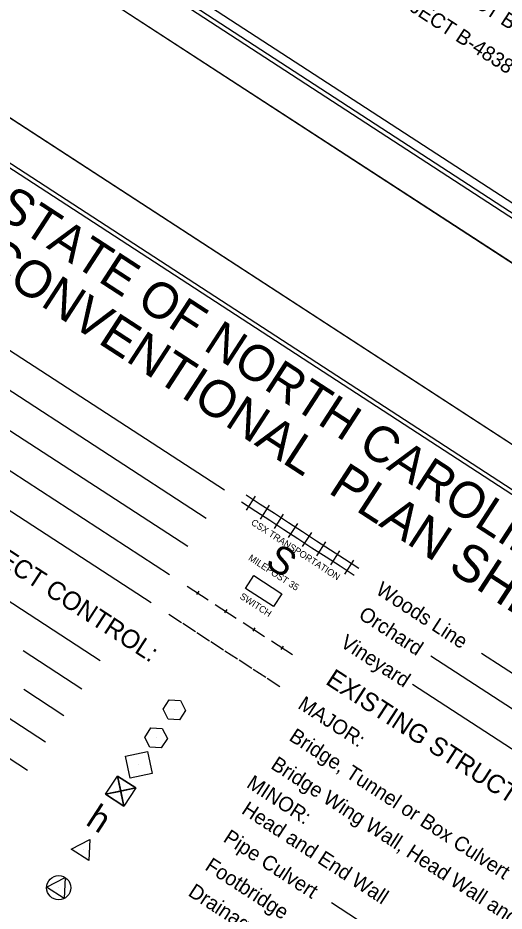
# Model space of a CAD drawing. Extents: x 2291197 to 2302790, y 592892 to 604246.
# Drawn here: x 2295608 to 2296768, y 597065 to 599195 of the extents above; entities that cross this region are included whole.
import ezdxf

# ---------------------------------------------------------------- set-up
doc = ezdxf.new("R2010")
doc.units = 0
for name, color, linetype in [('Default', 7, 'Continuous'), ('Prop Shade Light', 7, 'Continuous'), ('Sheet Cutting Line CELL', 7, 'Continuous'), ('Sheet Plot Border Inside CELL', 7, 'Continuous'), ('Sheet Plot Border Outside CELL', 7, 'Continuous'), ('Sheet Symbology CELL', 7, 'Continuous'), ('Sheet Title CELL', 7, 'Continuous')]:
    doc.layers.add(name, color=color, linetype=linetype)

# ---------------------------------------------------------------- blocks, each defined once
blk = doc.blocks.new('RWCON')
at = {"layer": 'Sheet Symbology CELL'}
blk.add_line((0, 0), (0, 0), dxfattribs=at)
blk.add_lwpolyline([(-0.125, -0.072), (0, 0.144), (0.125, -0.072)], close=True, dxfattribs=at)
blk.add_circle((0, 0), 0.144, dxfattribs=at)
blk = doc.blocks.new('CTL SECONDARY HORIZONTAL AND VERTICAL')
at = {"layer": 'Default'}
blk.add_line((0, 0), (0, 0), dxfattribs=at)
blk.add_lwpolyline([(-0.0735, 0.074), (0.07475, 0.074), (0.07475, -0.0745), (-0.0735, -0.0745)], close=True, dxfattribs=at)
blk = doc.blocks.new('CTL PRIMARY HORIZONTAL')
at = {"layer": 'Default'}
blk.add_line((0, 0), (0, 0), dxfattribs=at)
blk.add_lwpolyline([(0, -0.07375), (-0.06425, -0.03725), (-0.06425, 0.0365), (0, 0.07375), (0.06425, 0.03725), (0.06425, -0.03725), (0, -0.07375)], dxfattribs=at)
blk = doc.blocks.new('CTL PRIMARY HORIZONTAL AND VERTICAL')
at = {"layer": 'Default'}
blk.add_line((0, 0), (0, 0), dxfattribs=at)
blk.add_lwpolyline([(-0.0646, 0.0374), (0.0004, 0.0737), (0.0654, 0.0379), (0.0644, -0.0366), (-0.0006, -0.0743), (-0.0646, -0.0381)], close=True, dxfattribs=at)
blk = doc.blocks.new('CTL VERTICAL BENCHMARK')
at = {"layer": 'Default'}
blk.add_line((0, 0), (0, 0), dxfattribs=at)
blk.add_lwpolyline([(-0.072, 0.07175), (0.07175, 0.07175), (0.07175, -0.072), (-0.072, -0.072)], close=True, dxfattribs=at)
for points in [[(0.07175, 0.07175), (-0.072, -0.072), (-0.000125, -0.000125), (0.07175, -0.072), (-0.072, 0.07175)], [(-0.000125, -0.000125), (0.07175, 0.07175), (-0.072, 0.07175), (-0.000125, -0.000125)], [(-0.000125, -0.000125), (-0.072, -0.072), (0.07175, -0.072), (-0.000125, -0.000125)]]:
    blk.add_lwpolyline(points, dxfattribs=at)
blk = doc.blocks.new('PRRM')
at = {"layer": 'Sheet Symbology CELL'}
blk.add_line((0, 0), (0, 0), dxfattribs=at)
blk.add_lwpolyline([(-0.125, -0.072), (0, 0.144), (0.125, -0.072)], close=True, dxfattribs=at)
blk = doc.blocks.new('PLAN SHEET SYMBOLOGY - New')
at = {"layer": 'Sheet Cutting Line CELL'}
blk.add_line((1439376.56, 921733.15), (1437692.56, 921733.15), dxfattribs=at)
at = {"layer": 'Sheet Plot Border Inside CELL'}
blk.add_lwpolyline([(1437705.56, 920655.6), (1439372.06, 920655.6), (1439372.06, 921710.7), (1437705.56, 921710.7)], close=True, dxfattribs=at)
at = {"layer": 'Sheet Plot Border Outside CELL'}
blk.add_lwpolyline([(1437692.56, 920633.15), (1439376.56, 920633.15), (1439376.56, 921733.15), (1437692.56, 921733.15)], close=True, dxfattribs=at)
at = {"layer": 'Sheet Symbology CELL'}
for p, q in [((1438527.58, 921621.6), (1438537.58, 921621.6)), ((1438532.58, 921614.1), (1438532.58, 921624.1)), ((1438537.58, 921621.6), (1438547.58, 921621.6)), ((1438542.58, 921614.1), (1438542.58, 921624.1)), ((1438547.58, 921621.6), (1438557.58, 921621.6)), ((1438552.58, 921614.1), (1438552.58, 921624.1)), ((1438557.58, 921621.6), (1438567.58, 921621.6)), ((1438562.58, 921614.1), (1438562.58, 921624.1)), ((1438567.58, 921621.6), (1438577.58, 921621.6)), ((1438572.58, 921614.1), (1438572.58, 921624.1)), ((1438577.58, 921621.6), (1438587.58, 921621.6)), ((1438582.58, 921614.1), (1438582.58, 921624.1)), ((1438587.58, 921621.6), (1438597.58, 921621.6)), ((1438592.58, 921614.1), (1438592.58, 921624.1)), ((1438597.58, 921621.6), (1438607.58, 921621.6)), ((1438602.58, 921614.1), (1438602.58, 921624.1)), ((1438515.19, 921616.84), (1438356.78, 921616.84)), ((1438527.58, 921616.6), (1438537.58, 921616.6)), ((1438537.58, 921616.6), (1438547.58, 921616.6)), ((1438547.58, 921616.6), (1438557.58, 921616.6)), ((1438557.58, 921616.6), (1438567.58, 921616.6)), ((1438567.58, 921616.6), (1438577.58, 921616.6)), ((1438577.58, 921616.6), (1438587.58, 921616.6)), ((1438587.58, 921616.6), (1438597.58, 921616.6)), ((1438597.58, 921616.6), (1438607.58, 921616.6)), ((1438877.82, 921618.88), (1438696.7, 921618.88)), ((1438877.26, 921600.96), (1438672.32, 921600.96)), ((1438515.19, 921596.84), (1438365.64, 921596.84)), ((1438515.19, 921576.84), (1438300.28, 921576.84)), ((1438877.26, 921580.96), (1438672.32, 921580.96)), ((1438515.19, 921556.84), (1438349.03, 921556.84)), ((1438527.58, 921556.84), (1438542.58, 921556.84)), ((1438535.08, 921558.09), (1438535.08, 921555.59)), ((1438547.58, 921556.84), (1438562.58, 921556.84)), ((1438555.08, 921558.09), (1438555.08, 921555.59)), ((1438567.58, 921556.84), (1438582.58, 921556.84)), ((1438575.08, 921558.09), (1438575.08, 921555.59)), ((1438587.58, 921556.84), (1438602.58, 921556.84)), ((1438595.08, 921558.09), (1438595.08, 921555.59)), ((1438515.19, 921536.84), (1438349.03, 921536.84)), ((1438515.19, 921536.84), (1438349.03, 921536.84)), ((1438527.58, 921536.84), (1438536.58, 921536.84)), ((1438537.58, 921536.84), (1438546.58, 921536.84)), ((1438547.58, 921536.84), (1438556.58, 921536.84)), ((1438557.58, 921536.84), (1438566.58, 921536.84)), ((1438567.58, 921536.84), (1438576.58, 921536.84)), ((1438577.58, 921536.84), (1438586.58, 921536.84)), ((1438587.58, 921536.84), (1438596.58, 921536.84)), ((1438597.58, 921536.84), (1438606.58, 921536.84)), ((1438508.5, 921491.22), (1438417.47, 921491.22)), ((1438508.5, 921471.22), (1438466.58, 921471.22)), ((1438508.18, 921452.01), (1438479.63, 921452.01)), ((1438872.94, 921445.46), (1438702.75, 921445.46)), ((1438507.49, 921432.79), (1438368.65, 921432.79)), ((1438507.81, 921412.81), (1438435.76, 921412.81))]:
    blk.add_line(p, q, dxfattribs=at)
for points in [[(1439359.56, 921708.15), (1437859.56, 921708.15), (1437859.56, 920659.17), (1439359.56, 920659.17)], [(1438557.58, 921583.8), (1438577.58, 921583.8), (1438577.58, 921574.7), (1438557.58, 921574.7)]]:
    blk.add_lwpolyline(points, close=True, dxfattribs=at)
at = {"layer": 'Default'}
for name, p, xscale, yscale in [('CTL PRIMARY HORIZONTAL', (1438561.43, 921490.85), 90.22069107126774, 90.22069107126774), ('CTL PRIMARY HORIZONTAL AND VERTICAL', (1438561.42, 921470.88), 90.22069107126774, 90.22069107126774), ('CTL VERTICAL BENCHMARK', (1438561.05, 921432.81), 90.22069107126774, 90.22069107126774), ('PRRM', (1438561.42, 921391.41), 50, 50), ('RWCON', (1438561.44, 921364.35), 50, 50)]:
    blk.add_blockref(name, p, dxfattribs=dict(at, xscale=xscale, yscale=yscale))
at = {"layer": 'Default', "xscale": 90.22069107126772, "yscale": 90.22069107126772, "rotation": 45}
blk.add_blockref('CTL SECONDARY HORIZONTAL AND VERTICAL', (1438561.56, 921451.81), dxfattribs=at)
at = {"layer": 'Sheet Symbology CELL'}
for s, height, p in [('STATE OF NORTH CAROLINA, DIVISION OF HIGHWAYS', 21.419, (1438310.12, 921680.19)), ('CONVENTIONAL  PLAN SHEET SYMBOLS', 22.0323, (1438318.25, 921649.31)), ('Woods Line', 8.75, (1438623.66, 921614.36)), ('S', 16.5, (1438559.34, 921592.22)), ('Orchard', 8.75, (1438623.09, 921596.43)), ('Vineyard', 8.75, (1438623.09, 921576.43)), ('EXISTING STRUCTURES:', 11, (1438627.98, 921552.9)), ('MAJOR:', 8.75, (1438621.95, 921531.79)), ('Bridge, Tunnel or Box Culvert', 8.75, (1438627.98, 921512.9)), ('RIGHT OF WAY & PROJECT CONTROL:', 11, (1438259.89, 921506.56)), ('Bridge Wing Wall, Head Wall and End Wall', 8.75, (1438627.98, 921492.9)), ('MINOR:', 8.75, (1438621.95, 921475.66)), ('Head and End Wall', 8.75, (1438627.98, 921460.91)), ('Pipe Culvert', 8.75, (1438627.98, 921440.92)), ('Footbridge', 8.75, (1438627.99, 921420.92)), ('h', 15, (1438553.66, 921404.63)), ('Drainage Box: Catch Basin, DI or JB', 8.75, (1438627.99, 921402.48))]:
    blk.add_text(s, height=height, dxfattribs=at).set_placement(p)
for s, p in [('CSX TRANSPORTATION', (1438539.14, 921608.37)), ('MILEPOST 35', (1438549.33, 921589.79)), ('SWITCH', (1438557.53, 921567.79))]:
    blk.add_text(s, height=4, rotation=360, dxfattribs=at).set_placement(p)

msp = doc.modelspace()

# ---------------------------------------------------------------- linework, layer by layer
at = {"layer": 'Sheet Cutting Line CELL'}
for p, q in [((2293793.6, 600557.1), (2299441.2, 596885.8)), ((2299242.9, 596580.9), (2293595.3, 600252.2))]:
    msp.add_line(p, q, dxfattribs=at)
at = {"layer": 'Sheet Plot Border Inside CELL'}
msp.add_lwpolyline([(2293886.1, 600604), (2299475, 596970.9), (2301775.2, 600509.4), (2296186.3, 604142.5)], close=True, dxfattribs=at)
at = {"layer": 'Sheet Plot Border Outside CELL'}
msp.add_lwpolyline([(2301839.2, 600574.8), (2296191.6, 604246.1), (2293793.6, 600557.1), (2299441.2, 596885.8)], close=True, dxfattribs=at)
at = {"layer": 'Sheet Title CELL'}
for points in [[(2294441.6, 600255), (2299405.1, 597028.5)], [(2295777.2, 599410.7), (2297051.6, 598582.2)]]:
    msp.add_lwpolyline(points, dxfattribs=at)

# ---------------------------------------------------------------- block references
at = {"layer": 'Prop Shade Light', "xscale": 4, "yscale": 3.9999999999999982, "rotation": -33.02629958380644}
msp.add_blockref('PLAN SHEET SYMBOLOGY - New', (-4537434.8, 643359.8), dxfattribs=at)

# ---------------------------------------------------------------- texts
at = {"layer": 'Sheet Title CELL'}
for s, p in [('LENGTH STRUCTURE TIP PROJECT B-4838', (2296065, 599632.1)), ('TOTAL LENGTH TIP PROJECT B-4838', (2296073.7, 599516.6))]:
    msp.add_text(s, height=35.125, rotation=326.9737, dxfattribs=at).set_placement(p)

doc.saveas('drawing.dxf')
